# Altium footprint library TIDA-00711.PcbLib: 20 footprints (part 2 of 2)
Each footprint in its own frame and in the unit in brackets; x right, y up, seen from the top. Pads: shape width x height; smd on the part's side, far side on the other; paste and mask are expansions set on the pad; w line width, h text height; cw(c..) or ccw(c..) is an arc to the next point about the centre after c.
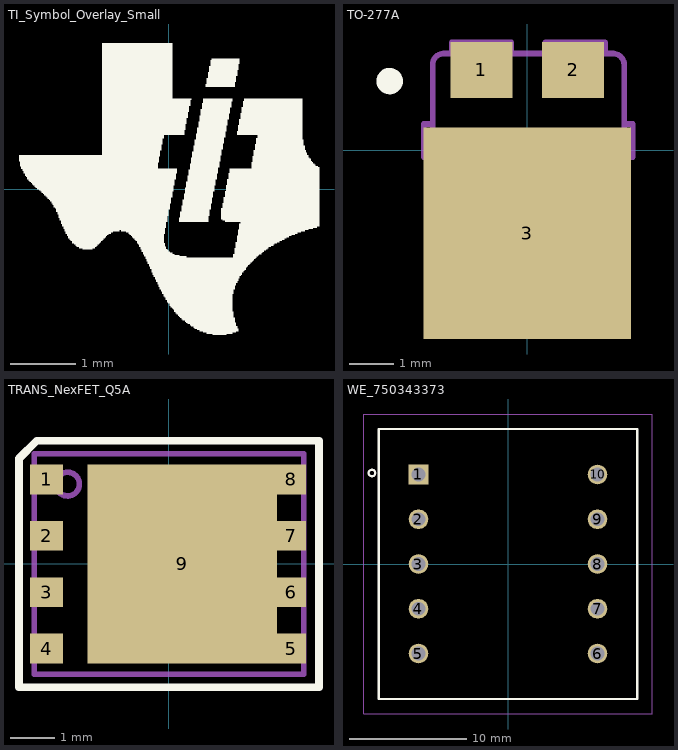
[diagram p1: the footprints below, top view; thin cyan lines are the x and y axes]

## TI_Symbol_Overlay_Small [mm]
height 28.5
Top Overlay:
  drawing of 3 lines, arcs and shapes, not listed

## TO-277A [mm] "Vishay"
height 1.2
pads (3):
  rect 1.4x1.27 smd: 1(-1.04,1.83) 2(1.04,1.83)
  rect 4.72x4.8 smd: 3(0,-1.883)
Top Overlay:
  circle w0.3: c-3.124,1.575 r0.15
Mechanical 5:
  lines w0.127: -2.15,-0.15 -2.35,-0.15 -2.35,0.6 -2.15,0.6 ; -1.715,2.2 -1.715,2.45 -0.365,2.45 -0.365,2.2 ; -1.075,-3.95 -1.075,-4.2 1.125,-4.2 1.125,-3.95 ; 0.415,2.2 0.415,2.45 1.765,2.45 1.765,2.2 ; 2.2,-0.15 2.4,-0.15 2.4,0.6 2.2,0.6 ; -2.15,-3.7 ccw(c-1.9,-3.7) -1.9,-3.95 1.95,-3.95 ccw(c1.95,-3.7) 2.2,-3.7 2.2,1.95 ccw(c1.95,1.95) 1.95,2.2 -1.9,2.2 ccw(c-1.9,1.95) -2.15,1.95 -2.15,-3.7
  text ".Designator" at -0.635,-1.372 h1.02
3D body: height 1.2, standoff 0, extent -2.35,-4.2 2.4,2.45

## TRANS_NexFET_Q5A [mm] "TI recommended land pattern (nominal) M0139-01"
height 1.1
pads (9):
  rect 0.75x0.675 smd paste-0.1 mask+0.051: 1(-2.776,1.917) 2(-2.776,0.639) 3(-2.776,-0.639) 4(-2.776,-1.917)
  rect 0.655x0.675 smd paste-0.1 mask+0.051: 5(2.776,-1.917) 6(2.776,-0.639) 7(2.776,0.639) 8(2.776,1.917)
  rect 4.295x4.51 smd paste-2.2 mask+0.051: 9(0.301,0)
Top Overlay:
  lines w0.178: -3.4,-2.795 -3.4,0 -3.4,2.39 -2.995,2.795 0,2.795 3.4,2.795 3.4,0 3.4,-2.795 0,-2.795 -3.4,-2.795
Top Paste:
  region: -1.412,-0.31 -1.412,-1.88 -0.177,-1.88 -0.177,-0.31
  region: -1.412,0.31 -1.412,1.88 -0.177,1.88 -0.177,0.31
  region: 0.323,-0.31 0.323,-1.88 1.908,-1.88 1.908,-0.31
  region: 0.323,0.31 0.323,1.88 1.908,1.88 1.908,0.31
Mechanical 5:
  circle w0.127: c-2.3,1.81 r0.269
  lines w0.127: -3.05,-2.5 -3.05,2.5 3.05,2.5 3.05,-2.5 -3.05,-2.5
  text ".Designator" at 0.914,0.559 h1.02
3D body: height 1.11, standoff 0, extent -3.05,-2.5 3.05,2.5

## WE_750343373 [mm] "TRANSFOERMER, TH, 10-PIN"
height 17.53
pads (10):
  rect 1.67x1.67 / inner round 1.67 / far side rect 1.67x1.67 hole 1.17: 1(-7.62,7.62)
  round 1.67 hole 1.17: 2(-7.62,3.81) 3(-7.62,0) 4(-7.62,-3.81) 5(-7.62,-7.62) 6(7.62,-7.62) 7(7.62,-3.81) 8(7.62,0) 9(7.62,3.81) 10(7.62,7.62)
Top Overlay:
  circle w0.178: c-11.584,7.747 r0.279
  lines w0.178: -11,-11.5 11,-11.5 11,11.5 -11,11.5 -11,-11.5
  text ".Designator" at -12.55,9.596 h0.76
Mechanical 5:
  circle w0.127: c-11.584,7.747 r0.279
  lines w0.127: -11,-11.5 11,-11.5 11,11.5 -11,11.5 -11,-11.5
  text ".Designator" at -1.524,-0.508 h1.02
Mechanical 15:
  lines w0.05: -12.27,-12.77 -12.27,12.77 12.27,12.77 12.27,-12.77 -12.27,-12.77
Mechanical 17:
  text "LEAD LENGTH MAX: 4:00 MM" at -11.684,9.652 h1
3D body: height 17.53, standoff 0, extent -11,-11.5 11,11.5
